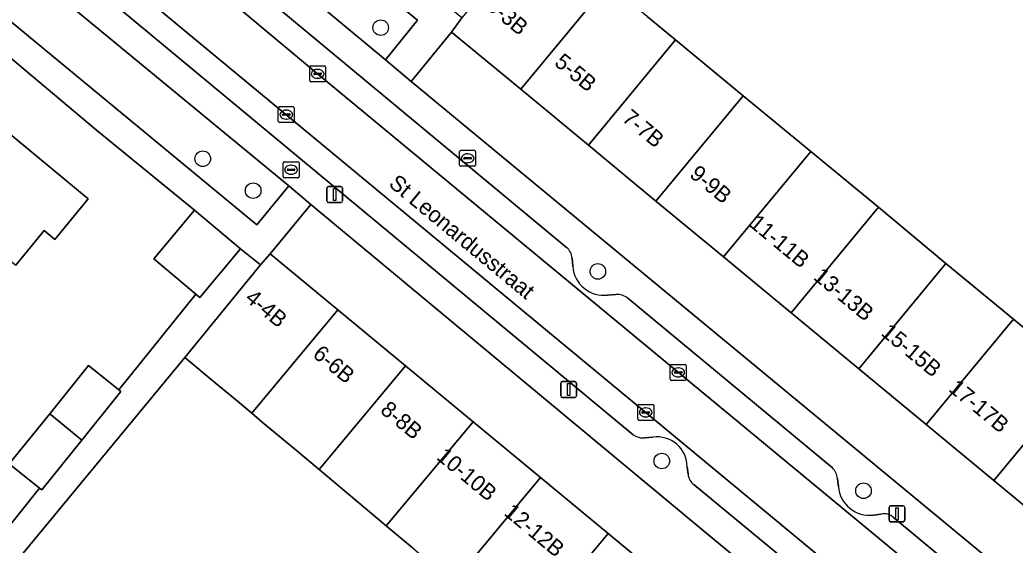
# Model space of a CAD drawing. Extents: x 162073 to 163043, y 381818 to 382561.
# Drawn here: x 162449 to 162511.6, y 382214.3 to 382247.3 of the extents above; entities that cross this region are included whole.
import ezdxf

# ---------------------------------------------------------------- set-up
doc = ezdxf.new("R2010")
doc.units = 0
for name, color, linetype in [('IMGEO_Boom', 7, 'Continuous'), ('IMGEO_Brandkraan', 7, 'Continuous'), ('IMGEO_Erf', 7, 'Continuous'), ('IMGEO_Groenvoorziening', 7, 'Continuous'), ('IMGEO_Kolk', 7, 'Continuous'), ('IMGEO_Lichtmast', 7, 'Continuous'), ('IMGEO_Muur', 7, 'Continuous'), ('IMGEO_Openbare_ruimte_label', 7, 'Continuous'), ('IMGEO_Pand', 7, 'Continuous'), ('IMGEO_Pand_nummerreeks', 7, 'Continuous'), ('IMGEO_Parkeervlak_open', 7, 'Continuous'), ('IMGEO_Rijbaan_lokaal_open', 7, 'Continuous'), ('IMGEO_Rioolput', 7, 'Continuous'), ('IMGEO_Voetpad_open', 7, 'Continuous')]:
    doc.layers.add(name, color=color, linetype=linetype)

msp = doc.modelspace()

# ---------------------------------------------------------------- linework, layer by layer
at = {"layer": 'IMGEO_Boom'}
for centre in [(162471.704, 382246.766), (162460.522, 382238.531), (162463.692, 382236.523), (162485.349, 382231.451), (162489.366, 382219.536), (162502.038, 382217.668)]:
    msp.add_circle(centre, 0.489, dxfattribs=at)
at = {"layer": 'IMGEO_Brandkraan'}
for p, q in [((162476.665, 382238.132), (162476.665, 382238.984)), ((162476.74, 382239.058), (162477.592, 382239.058)), ((162476.967, 382238.601), (162477.365, 382238.601)), ((162477.153, 382238.838), (162477.178, 382238.838)), ((162477.666, 382238.984), (162477.666, 382238.132)), ((162477.592, 382238.058), (162476.74, 382238.058)), ((162476.924, 382238.552), (162476.924, 382238.564)), ((162477.362, 382238.515), (162476.964, 382238.515)), ((162477.176, 382238.278), (162477.151, 382238.278)), ((162477.408, 382238.564), (162477.408, 382238.552))]:
    msp.add_line(p, q, dxfattribs=at)
for points in [[(162476.665, 382238.132), (162476.665, 382238.984)], [(162476.74, 382239.058), (162477.592, 382239.058)], [(162477.666, 382238.984), (162477.666, 382238.132)], [(162477.592, 382238.058), (162476.74, 382238.058)]]:
    msp.add_lwpolyline(points, dxfattribs=at)
for centre, radius, start, end in [((162476.742, 382238.982), 0.0765, 91.55205, 178.44795), ((162476.742, 382238.982), 0.0765, 91.55205, 178.44795), ((162476.964, 382238.561), 0.0403, 85.87752, 175.75265), ((162477.369, 382238.563), 0.0386, 1.73085, 96.63898), ((162477.59, 382238.982), 0.0765, 1.55205, 88.44795), ((162477.59, 382238.982), 0.0765, 1.55205, 88.44795), ((162476.742, 382238.134), 0.0765, 181.55205, 268.44795), ((162476.742, 382238.134), 0.0765, 181.55205, 268.44795), ((162476.961, 382238.551), 0.0366, 178.93798, 274.71019), ((162477.365, 382238.558), 0.043, 264.86636, 352.45326), ((162477.59, 382238.134), 0.0765, 271.55205, 358.44795), ((162477.59, 382238.134), 0.0765, 271.55205, 358.44795)]:
    msp.add_arc(centre, radius, start, end, dxfattribs=at)
for centre, major_axis, ratio, start_param, end_param in [((162477.152, 382238.558), (-0.387, 0.002), 0.722429, 4.712389, 7.853982), ((162477.177, 382238.558), (-0.39, 0.002), 0.717154, 1.570796, 4.712389)]:
    msp.add_ellipse(centre, major_axis=major_axis, ratio=ratio, start_param=start_param, end_param=end_param, dxfattribs=at)
at = {"layer": 'IMGEO_Erf'}
for points in [[(162488.441, 382247.475), (162490.227, 382246), (162494.475, 382242.489), (162498.723, 382238.979), (162502.983, 382235.483), (162507.218, 382231.957), (162511.467, 382228.446), (162515.715, 382224.935), (162519.963, 382221.424), (162521.15, 382220.534), (162522.293, 382219.59), (162524.256, 382217.968), (162525.735, 382216.712), (162527.111, 382215.574), (162528.486, 382214.436), (162530.21, 382213.011), (162530.869, 382212.466), (162532.717, 382210.905), (162534.226, 382209.657), (162535.316, 382208.756), (162536.964, 382207.393), (162546.943, 382219.45), (162494.331, 382268.629)], [(162445.668, 382216.267), (162447.701, 382214.63), (162450.274, 382217.827), (162448.372, 382219.358), (162450.909, 382222.51), (162453.344, 382225.536), (162455.245, 382224.005), (162460.094, 382230.03), (162457.457, 382232.246), (162459.998, 382235.296), (162453.858, 382240.334), (162447.496, 382245.651)], [(162445.122, 382242.796), (162453.328, 382236.001), (162451.227, 382233.463), (162450.568, 382234.014), (162448.774, 382231.847)], [(162473.683, 382214.093), (162472.05, 382215.455), (162467.837, 382219.006), (162466.41, 382220.197), (162464.266, 382221.986), (162463.605, 382222.537), (162462.453, 382223.497), (162461.302, 382224.456), (162459.396, 382226.044), (162434.47, 382195.892)]]:
    msp.add_lwpolyline(points, dxfattribs=at)
for points in [[(162473.626, 382243.391), (162528.918, 382197.653), (162531.465, 382200.747), (162527.218, 382204.259), (162522.971, 382207.772), (162518.724, 382211.284), (162514.477, 382214.796), (162510.231, 382218.308), (162505.984, 382221.82), (162501.737, 382225.333), (162497.49, 382228.845), (162493.243, 382232.357), (162488.996, 382235.869), (162484.75, 382239.382), (162480.503, 382242.894), (162476.155, 382246.489)], [(162464.763, 382232.548), (162469.013, 382229.032), (162473.259, 382225.518), (162477.505, 382222.005), (162481.751, 382218.492), (162485.997, 382214.978), (162490.243, 382211.465), (162494.489, 382207.952), (162498.734, 382204.438), (162502.98, 382200.925), (162507.226, 382197.412), (162511.472, 382193.898), (162515.718, 382190.385), (162519.964, 382186.872), (162522.479, 382189.936), (162491.963, 382215.169), (162467.32, 382235.647)]]:
    msp.add_lwpolyline(points, close=True, dxfattribs=at)
at = {"layer": 'IMGEO_Groenvoorziening'}
for points in [[(162471.998, 382244.738), (162474.021, 382247.229), (162457.906, 382260.427), (162455.97, 382258.081)], [(162463.917, 382234.37), (162465.927, 382236.819), (162449.526, 382250.362), (162447.507, 382247.934)]]:
    msp.add_lwpolyline(points, close=True, dxfattribs=at)
at = {"layer": 'IMGEO_Kolk'}
for p, q in [((162467.242, 382243.437), (162467.242, 382244.289)), ((162467.317, 382244.363), (162468.169, 382244.363)), ((162468.243, 382244.289), (162468.243, 382243.437)), ((162467.501, 382243.857), (162467.501, 382243.869)), ((162467.939, 382243.82), (162467.541, 382243.82)), ((162467.544, 382243.906), (162467.942, 382243.906)), ((162467.753, 382243.583), (162467.728, 382243.583)), ((162467.73, 382244.143), (162467.755, 382244.143)), ((162467.985, 382243.869), (162467.985, 382243.857)), ((162468.169, 382243.363), (162467.317, 382243.363)), ((162465.273, 382240.876), (162465.273, 382241.728)), ((162465.348, 382241.802), (162466.2, 382241.802)), ((162466.274, 382241.728), (162466.274, 382240.876)), ((162465.532, 382241.296), (162465.532, 382241.308)), ((162465.97, 382241.259), (162465.572, 382241.259)), ((162465.575, 382241.345), (162465.973, 382241.345)), ((162465.761, 382241.582), (162465.786, 382241.582)), ((162466.016, 382241.308), (162466.016, 382241.296)), ((162466.2, 382240.802), (162465.348, 382240.802)), ((162465.784, 382241.022), (162465.759, 382241.022)), ((162489.896, 382224.679), (162489.896, 382225.531)), ((162489.971, 382225.605), (162490.823, 382225.605)), ((162490.897, 382225.531), (162490.897, 382224.679)), ((162490.155, 382225.099), (162490.155, 382225.111)), ((162490.593, 382225.062), (162490.195, 382225.062)), ((162490.198, 382225.148), (162490.596, 382225.148)), ((162490.407, 382224.825), (162490.382, 382224.825)), ((162490.384, 382225.385), (162490.409, 382225.385)), ((162490.639, 382225.111), (162490.639, 382225.099)), ((162490.823, 382224.605), (162489.971, 382224.605)), ((162487.856, 382222.165), (162487.856, 382223.017)), ((162487.931, 382223.091), (162488.783, 382223.091)), ((162488.857, 382223.017), (162488.857, 382222.165)), ((162488.115, 382222.585), (162488.115, 382222.597)), ((162488.553, 382222.548), (162488.155, 382222.548)), ((162488.158, 382222.634), (162488.556, 382222.634)), ((162488.344, 382222.871), (162488.369, 382222.871)), ((162488.599, 382222.597), (162488.599, 382222.585)), ((162488.783, 382222.091), (162487.931, 382222.091)), ((162488.367, 382222.311), (162488.342, 382222.311))]:
    msp.add_line(p, q, dxfattribs=at)
for points in [[(162467.242, 382243.437), (162467.242, 382244.289)], [(162467.317, 382244.363), (162468.169, 382244.363)], [(162468.243, 382244.289), (162468.243, 382243.437)], [(162468.169, 382243.363), (162467.317, 382243.363)], [(162465.273, 382240.876), (162465.273, 382241.728)], [(162465.348, 382241.802), (162466.2, 382241.802)], [(162466.274, 382241.728), (162466.274, 382240.876)], [(162466.2, 382240.802), (162465.348, 382240.802)], [(162489.896, 382224.679), (162489.896, 382225.531)], [(162489.971, 382225.605), (162490.823, 382225.605)], [(162490.897, 382225.531), (162490.897, 382224.679)], [(162490.823, 382224.605), (162489.971, 382224.605)], [(162487.856, 382222.165), (162487.856, 382223.017)], [(162487.931, 382223.091), (162488.783, 382223.091)], [(162488.857, 382223.017), (162488.857, 382222.165)], [(162488.783, 382222.091), (162487.931, 382222.091)]]:
    msp.add_lwpolyline(points, dxfattribs=at)
for centre, radius, start, end in [((162467.319, 382244.287), 0.0765, 91.55205, 178.44795), ((162467.319, 382244.287), 0.0765, 91.55205, 178.44795), ((162468.167, 382244.287), 0.0765, 1.55205, 88.44795), ((162468.167, 382244.287), 0.0765, 1.55205, 88.44795), ((162467.541, 382243.866), 0.0403, 85.87752, 175.75265), ((162467.538, 382243.856), 0.0366, 178.93798, 274.71019), ((162467.942, 382243.863), 0.043, 264.86636, 352.45326), ((162467.946, 382243.868), 0.0386, 1.73085, 96.63898), ((162467.319, 382243.439), 0.0765, 181.55205, 268.44795), ((162467.319, 382243.439), 0.0765, 181.55205, 268.44795), ((162468.167, 382243.439), 0.0765, 271.55205, 358.44795), ((162468.167, 382243.439), 0.0765, 271.55205, 358.44795), ((162465.35, 382241.726), 0.0765, 91.55205, 178.44795), ((162465.35, 382241.726), 0.0765, 91.55205, 178.44795), ((162466.198, 382241.726), 0.0765, 1.55205, 88.44795), ((162466.198, 382241.726), 0.0765, 1.55205, 88.44795), ((162465.572, 382241.305), 0.0403, 85.87752, 175.75265), ((162465.569, 382241.295), 0.0366, 178.93798, 274.71019), ((162465.973, 382241.302), 0.043, 264.86636, 352.45326), ((162465.977, 382241.307), 0.0386, 1.73085, 96.63898), ((162465.35, 382240.878), 0.0765, 181.55205, 268.44795), ((162465.35, 382240.878), 0.0765, 181.55205, 268.44795), ((162466.198, 382240.878), 0.0765, 271.55205, 358.44795), ((162466.198, 382240.878), 0.0765, 271.55205, 358.44795), ((162489.973, 382225.529), 0.0765, 91.55205, 178.44795), ((162489.973, 382225.529), 0.0765, 91.55205, 178.44795), ((162490.821, 382225.529), 0.0765, 1.55205, 88.44795), ((162490.821, 382225.529), 0.0765, 1.55205, 88.44795), ((162490.195, 382225.108), 0.0403, 85.87752, 175.75265), ((162490.192, 382225.098), 0.0366, 178.93798, 274.71019), ((162490.596, 382225.105), 0.043, 264.86636, 352.45326), ((162490.6, 382225.11), 0.0386, 1.73085, 96.63898), ((162489.973, 382224.681), 0.0765, 181.55205, 268.44795), ((162489.973, 382224.681), 0.0765, 181.55205, 268.44795), ((162490.821, 382224.681), 0.0765, 271.55205, 358.44795), ((162490.821, 382224.681), 0.0765, 271.55205, 358.44795), ((162487.933, 382223.015), 0.0765, 91.55205, 178.44795), ((162487.933, 382223.015), 0.0765, 91.55205, 178.44795), ((162488.781, 382223.015), 0.0765, 1.55205, 88.44795), ((162488.781, 382223.015), 0.0765, 1.55205, 88.44795), ((162488.155, 382222.594), 0.0403, 85.87752, 175.75265), ((162488.152, 382222.584), 0.0366, 178.93798, 274.71019), ((162488.556, 382222.591), 0.043, 264.86636, 352.45326), ((162488.56, 382222.596), 0.0386, 1.73085, 96.63898), ((162487.933, 382222.167), 0.0765, 181.55205, 268.44795), ((162487.933, 382222.167), 0.0765, 181.55205, 268.44795), ((162488.781, 382222.167), 0.0765, 271.55205, 358.44795), ((162488.781, 382222.167), 0.0765, 271.55205, 358.44795)]:
    msp.add_arc(centre, radius, start, end, dxfattribs=at)
for centre, major_axis, ratio, start_param, end_param in [((162467.729, 382243.863), (-0.387, 0.002), 0.722429, 4.712389, 7.853982), ((162467.754, 382243.863), (-0.39, 0.002), 0.717154, 1.570796, 4.712389), ((162465.76, 382241.302), (-0.387, 0.002), 0.722429, 4.712389, 7.853982), ((162465.785, 382241.302), (-0.39, 0.002), 0.717154, 1.570796, 4.712389), ((162490.383, 382225.105), (-0.387, 0.002), 0.722429, 4.712389, 7.853982), ((162490.408, 382225.105), (-0.39, 0.002), 0.717154, 1.570796, 4.712389), ((162488.343, 382222.591), (-0.387, 0.002), 0.722429, 4.712389, 7.853982), ((162488.368, 382222.591), (-0.39, 0.002), 0.717154, 1.570796, 4.712389)]:
    msp.add_ellipse(centre, major_axis=major_axis, ratio=ratio, start_param=start_param, end_param=end_param, dxfattribs=at)
at = {"layer": 'IMGEO_Lichtmast'}
for p, q in [((162468.417, 382236.776), (162469.207, 382236.776)), ((162469.207, 382236.776), (162468.417, 382236.776)), ((162468.317, 382235.876), (162468.317, 382236.676)), ((162468.317, 382236.676), (162468.317, 382235.876)), ((162469.307, 382236.676), (162469.307, 382235.876)), ((162469.307, 382235.876), (162469.307, 382236.676)), ((162469.207, 382235.776), (162468.417, 382235.776)), ((162468.417, 382235.776), (162469.207, 382235.776)), ((162483.013, 382223.623), (162483.013, 382224.423)), ((162483.013, 382224.423), (162483.013, 382223.623)), ((162483.113, 382224.523), (162483.903, 382224.523)), ((162483.903, 382224.523), (162483.113, 382224.523)), ((162484.003, 382224.423), (162484.003, 382223.623)), ((162484.003, 382223.623), (162484.003, 382224.423)), ((162483.903, 382223.523), (162483.113, 382223.523)), ((162483.113, 382223.523), (162483.903, 382223.523)), ((162503.742, 382216.719), (162504.532, 382216.719)), ((162504.532, 382216.719), (162503.742, 382216.719)), ((162503.642, 382215.819), (162503.642, 382216.619)), ((162503.642, 382216.619), (162503.642, 382215.819)), ((162504.632, 382216.619), (162504.632, 382215.819)), ((162504.632, 382215.819), (162504.632, 382216.619)), ((162504.532, 382215.719), (162503.742, 382215.719)), ((162503.742, 382215.719), (162504.532, 382215.719))]:
    msp.add_line(p, q, dxfattribs=at)
for points in [[(162468.737, 382236.651), (162468.887, 382236.651), (162468.887, 382235.901), (162468.737, 382235.901), (162468.737, 382236.651)], [(162483.433, 382224.398), (162483.583, 382224.398), (162483.583, 382223.648), (162483.433, 382223.648), (162483.433, 382224.398)], [(162504.062, 382216.594), (162504.212, 382216.594), (162504.212, 382215.844), (162504.062, 382215.844), (162504.062, 382216.594)]]:
    msp.add_lwpolyline(points, dxfattribs=at)
for centre, start, end in [((162468.417, 382236.676), 90, 180), ((162468.417, 382236.676), 90, 180), ((162469.207, 382236.676), 0, 90), ((162469.207, 382236.676), 360, 90), ((162468.417, 382235.876), 180, 270), ((162468.417, 382235.876), 180, 270), ((162469.207, 382235.876), 270, 0), ((162469.207, 382235.876), 270, 0), ((162483.113, 382224.423), 90, 180), ((162483.113, 382224.423), 90, 180), ((162483.903, 382224.423), 0, 90), ((162483.903, 382224.423), 360, 90), ((162483.113, 382223.623), 180, 270), ((162483.113, 382223.623), 180, 270), ((162483.903, 382223.623), 270, 0), ((162483.903, 382223.623), 270, 0), ((162503.742, 382216.619), 90, 180), ((162503.742, 382216.619), 90, 180), ((162504.532, 382216.619), 0, 90), ((162504.532, 382216.619), 360, 90), ((162503.742, 382215.819), 180, 270), ((162503.742, 382215.819), 180, 270), ((162504.532, 382215.819), 270, 0), ((162504.532, 382215.819), 270, 0)]:
    msp.add_arc(centre, 0.1, start, end, dxfattribs=at)
at = {"layer": 'IMGEO_Muur'}
msp.add_lwpolyline([(162459.998, 382235.296), (162453.858, 382240.334)], dxfattribs=at)
at = {"layer": 'IMGEO_Pand'}
for points in [[(162485.979, 382249.511), (162483.952, 382251.186), (162483.282, 382251.74), (162481.569, 382253.156), (162476.81, 382247.387), (162476.155, 382246.489), (162480.503, 382242.894)], [(162490.227, 382246), (162488.441, 382247.475), (162485.979, 382249.511), (162480.503, 382242.894), (162484.75, 382239.382)], [(162494.475, 382242.489), (162490.227, 382246), (162484.75, 382239.382), (162488.996, 382235.869)], [(162441.225, 382238.09), (162448.774, 382231.847), (162450.568, 382234.014), (162451.227, 382233.463), (162453.328, 382236.001), (162445.122, 382242.796)], [(162498.723, 382238.979), (162494.475, 382242.489), (162488.996, 382235.869), (162493.243, 382232.357)], [(162502.983, 382235.483), (162498.723, 382238.979), (162493.243, 382232.357), (162497.49, 382228.845)], [(162507.218, 382231.957), (162502.983, 382235.483), (162497.49, 382228.845), (162501.737, 382225.333)], [(162462.887, 382232.868), (162459.998, 382235.296), (162457.457, 382232.246), (162460.094, 382230.03), (162460.346, 382229.818)], [(162469.013, 382229.032), (162464.763, 382232.548), (162464.155, 382231.869), (162459.396, 382226.044), (162461.302, 382224.456), (162462.453, 382223.497), (162463.605, 382222.537)], [(162511.467, 382228.446), (162507.218, 382231.957), (162501.737, 382225.333), (162505.984, 382221.82)], [(162473.259, 382225.518), (162469.013, 382229.032), (162463.605, 382222.537), (162464.266, 382221.986), (162466.41, 382220.197), (162467.837, 382219.006)], [(162515.715, 382224.935), (162511.467, 382228.446), (162505.984, 382221.82), (162510.231, 382218.308)], [(162455.377, 382223.899), (162455.245, 382224.005), (162453.344, 382225.536), (162450.909, 382222.51), (162452.92, 382220.847)], [(162477.505, 382222.005), (162473.259, 382225.518), (162467.837, 382219.006), (162472.05, 382215.455)], [(162519.963, 382221.424), (162515.715, 382224.935), (162510.231, 382218.308), (162514.477, 382214.796)], [(162452.92, 382220.847), (162450.909, 382222.51), (162448.372, 382219.358), (162450.274, 382217.827), (162450.405, 382217.722)], [(162481.751, 382218.492), (162477.505, 382222.005), (162472.05, 382215.455), (162473.683, 382214.093), (162474.61, 382213.32), (162476.283, 382211.925)], [(162485.997, 382214.978), (162481.751, 382218.492), (162476.283, 382211.925), (162478.131, 382210.408), (162480.527, 382208.41)], [(162490.243, 382211.465), (162485.997, 382214.978), (162480.527, 382208.41), (162481.278, 382207.784), (162483.217, 382206.167), (162484.818, 382204.95)]]:
    msp.add_lwpolyline(points, close=True, dxfattribs=at)
at = {"layer": 'IMGEO_Parkeervlak_open'}
for points in [[(162455.575, 382254.047), (162467.743, 382243.863), (162583.48, 382148.075)], [(162483.379, 382232.961), (162458.327, 382253.762)], [(162576.743, 382149.513), (162505.451, 382208.42), (162453.427, 382251.529)], [(162454.369, 382248.742), (162487.569, 382221.19)], [(162483.766, 382231.751), (162483.727, 382232.286)], [(162486.482, 382230.007), (162485.962, 382229.967)], [(162500.09, 382219.102), (162487.228, 382229.772)], [(162488.295, 382220.986), (162488.81, 382221.03)], [(162490.956, 382219.177), (162491.015, 382218.703)], [(162491.402, 382218.04), (162531.722, 382184.707)], [(162500.457, 382217.914), (162500.395, 382218.439)], [(162503.153, 382216.204), (162502.656, 382216.142)], [(162516.926, 382205.188), (162503.92, 382215.987)]]:
    msp.add_lwpolyline(points, dxfattribs=at)
for centre, radius, start, end in [((162482.762, 382232.216), 0.968, 4.1742, 50.37304), ((162485.721, 382231.913), 1.961, 184.74831, 277.07183), ((162486.536, 382228.877), 1.131, 52.29303, 92.73672), ((162488.212, 382222.085), 1.102, 234.30581, 274.30434), ((162489.085, 382219.179), 1.871, 359.94263, 98.43833), ((162491.942, 382218.8), 0.932, 185.96347, 234.58164), ((162499.33, 382218.351), 1.069, 4.74029, 44.66742), ((162502.417, 382218.096), 1.968, 185.29744, 276.97738), ((162503.325, 382215.348), 0.874, 47.0569, 101.34851)]:
    msp.add_arc(centre, radius, start, end, dxfattribs=at)
at = {"layer": 'IMGEO_Rijbaan_lokaal_open'}
msp.add_lwpolyline([(162599.371, 382134.967), (162586.579, 382145.506), (162586.493, 382145.572), (162583.59, 382147.984), (162583.48, 382148.075), (162467.743, 382243.863), (162455.575, 382254.047), (162453.427, 382251.529), (162505.451, 382208.42), (162576.743, 382149.513), (162581.599, 382145.482), (162584.507, 382143.092), (162586.648, 382141.318), (162597.298, 382132.492)], close=True, dxfattribs=at)
at = {"layer": 'IMGEO_Rioolput'}
for p, q in [((162465.574, 382237.411), (162465.574, 382238.263)), ((162465.649, 382238.337), (162466.501, 382238.337)), ((162466.062, 382238.117), (162466.087, 382238.117)), ((162466.575, 382238.263), (162466.575, 382237.411)), ((162466.501, 382237.337), (162465.649, 382237.337)), ((162465.833, 382237.831), (162465.833, 382237.843)), ((162466.271, 382237.794), (162465.873, 382237.794)), ((162465.876, 382237.88), (162466.274, 382237.88)), ((162466.085, 382237.557), (162466.06, 382237.557)), ((162466.317, 382237.843), (162466.317, 382237.831))]:
    msp.add_line(p, q, dxfattribs=at)
for points in [[(162465.574, 382237.411), (162465.574, 382238.263)], [(162465.649, 382238.337), (162466.501, 382238.337)], [(162466.575, 382238.263), (162466.575, 382237.411)], [(162466.501, 382237.337), (162465.649, 382237.337)]]:
    msp.add_lwpolyline(points, dxfattribs=at)
for centre, radius, start, end in [((162465.651, 382238.261), 0.0765, 91.55205, 178.44795), ((162465.651, 382238.261), 0.0765, 91.55205, 178.44795), ((162466.499, 382238.261), 0.0765, 1.55205, 88.44795), ((162466.499, 382238.261), 0.0765, 1.55205, 88.44795), ((162465.651, 382237.413), 0.0765, 181.55205, 268.44795), ((162465.651, 382237.413), 0.0765, 181.55205, 268.44795), ((162465.873, 382237.84), 0.0403, 85.87752, 175.75265), ((162465.87, 382237.83), 0.0366, 178.93798, 274.71019), ((162466.274, 382237.837), 0.043, 264.86636, 352.45326), ((162466.278, 382237.842), 0.0386, 1.73085, 96.63898), ((162466.499, 382237.413), 0.0765, 271.55205, 358.44795), ((162466.499, 382237.413), 0.0765, 271.55205, 358.44795)]:
    msp.add_arc(centre, radius, start, end, dxfattribs=at)
for centre, major_axis, ratio, start_param, end_param in [((162466.061, 382237.837), (-0.387, 0.002), 0.722429, 4.712389, 7.853982), ((162466.086, 382237.837), (-0.39, 0.002), 0.717154, 1.570796, 4.712389)]:
    msp.add_ellipse(centre, major_axis=major_axis, ratio=ratio, start_param=start_param, end_param=end_param, dxfattribs=at)
at = {"layer": 'IMGEO_Voetpad_open'}
for points in [[(162459.18, 382261.904), (162457.906, 382260.427), (162474.021, 382247.229), (162471.998, 382244.738), (162473.626, 382243.391), (162476.155, 382246.489), (162476.81, 382247.387), (162475.761, 382248.251)], [(162447.507, 382247.934), (162447.496, 382245.651), (162453.858, 382240.334), (162459.998, 382235.296), (162462.887, 382232.868), (162464.155, 382231.869), (162464.763, 382232.548), (162467.32, 382235.647), (162465.927, 382236.819), (162463.917, 382234.37)], [(162459.396, 382226.044), (162464.155, 382231.869), (162462.887, 382232.868), (162460.346, 382229.818), (162460.094, 382230.03), (162455.245, 382224.005), (162455.377, 382223.899), (162452.92, 382220.847), (162450.405, 382217.722), (162450.274, 382217.827), (162447.701, 382214.63), (162445.244, 382211.578), (162442.729, 382208.453), (162440.021, 382205.355), (162437.564, 382202.303), (162435.049, 382199.178), (162432.409, 382196.013), (162429.931, 382193.023), (162424.231, 382186.112), (162424.614, 382185.801), (162425.454, 382185.106), (162428.604, 382188.91), (162431.821, 382192.739), (162434.47, 382195.892)]]:
    msp.add_lwpolyline(points, close=True, dxfattribs=at)
for points in [[(162530.074, 382196.697), (162528.918, 382197.653), (162473.626, 382243.391), (162471.998, 382244.738), (162455.97, 382258.081), (162454.104, 382255.237), (162455.575, 382254.047)], [(162458.327, 382253.762), (162483.379, 382232.961)], [(162453.427, 382251.529), (162452.002, 382252.727), (162449.526, 382250.362), (162465.927, 382236.819), (162467.32, 382235.647), (162491.963, 382215.169), (162522.479, 382189.936), (162523.638, 382188.978), (162578.962, 382143.232), (162580.273, 382142.148), (162578.638, 382140.471), (162580.943, 382138.549), (162581.857, 382139.648), (162588.643, 382133.909), (162591.826, 382131.301), (162594.946, 382128.72), (162597.674, 382126.473), (162599.157, 382123.241)], [(162487.569, 382221.19), (162454.369, 382248.742)], [(162483.727, 382232.286), (162483.766, 382231.751)], [(162485.962, 382229.967), (162486.482, 382230.007)], [(162487.228, 382229.772), (162500.09, 382219.102)], [(162488.81, 382221.03), (162488.295, 382220.986)], [(162491.015, 382218.703), (162490.956, 382219.177)], [(162531.722, 382184.707), (162491.402, 382218.04)], [(162500.395, 382218.439), (162500.457, 382217.914)], [(162502.656, 382216.142), (162503.153, 382216.204)], [(162503.92, 382215.987), (162516.926, 382205.188)]]:
    msp.add_lwpolyline(points, dxfattribs=at)
for centre, radius, start, end in [((162482.762, 382232.216), 0.968, 4.1742, 50.37304), ((162485.721, 382231.913), 1.961, 184.74831, 277.07183), ((162486.536, 382228.877), 1.131, 52.29303, 92.73672), ((162488.212, 382222.085), 1.102, 234.30581, 274.30434), ((162489.085, 382219.179), 1.871, 359.94263, 98.43833), ((162491.942, 382218.8), 0.932, 185.96347, 234.58164), ((162499.33, 382218.351), 1.069, 4.74029, 44.66742), ((162502.417, 382218.096), 1.968, 185.29744, 276.97738), ((162503.325, 382215.348), 0.874, 47.0569, 101.34851)]:
    msp.add_arc(centre, radius, start, end, dxfattribs=at)

# ---------------------------------------------------------------- texts
at = {"layer": 'IMGEO_Openbare_ruimte_label'}
msp.add_text('St Leonardusstraat', height=1, rotation=320.35583, dxfattribs=at).set_placement((162472.147, 382236.856))
at = {"layer": 'IMGEO_Pand_nummerreeks'}
for s, rotation, p in [('3-3B', 320.40862, (162478.259, 382248.02)), ('5-5B', 320.40862, (162482.556, 382244.466)), ('7-7B', 320.40862, (162486.803, 382240.954)), ('9-9B', 320.40862, (162491.05, 382237.441)), ('11-11B', 320.40862, (162494.798, 382234.341)), ('13-13B', 320.40862, (162498.834, 382231.003)), ('4-4B', 320.39143, (162463.121, 382229.65)), ('15-15B', 320.40862, (162503.08, 382227.491)), ('6-6B', 320.39143, (162467.369, 382226.135)), ('17-17B', 320.40862, (162507.327, 382223.979)), ('8-8B', 320.39143, (162471.615, 382222.622)), ('10-10B', 320.39143, (162475.151, 382219.695)), ('12-12B', 320.39143, (162479.397, 382216.182))]:
    msp.add_text(s, height=1, rotation=rotation, dxfattribs=at).set_placement(p)

doc.saveas('drawing.dxf')
